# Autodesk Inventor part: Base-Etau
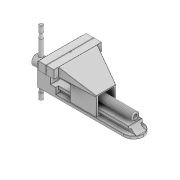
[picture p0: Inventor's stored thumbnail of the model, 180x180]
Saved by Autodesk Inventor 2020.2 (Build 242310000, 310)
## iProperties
Created: 2022-02
Part Number: Base-Etau
Material: Générique
Document SubType Name: Modeling
Designer: Philippe
Density: 1 g/cm^3
Appearance: Par défaut
Author: Philippe
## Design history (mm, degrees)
sketch "Esquisse1"
  geometry: L1 (0, 0)-(63.336, 0); L2 (0, 0)-(0, 50.188); L3 (-35.5, 12)-(-15, 12); L4 (-15, 12)-(-15, -22); L5 (-15, -22)-(-35.5, -22); L6 (-35.5, -22)-(-35.5, 12); L7 (-15, -22)-(113, -22); L8 (113, -22)-(113, -8); L9 (113, -8)-(-15, -8); L10 (-15, -8)-(-15, -22); L11 (0, 36)-(-12, 36); L12 (-12, 36)-(-12, 23); L13 (-12, 23)-(0, 23); L14 (0, 23)-(0, 36); L15 (0, 23)-(12, 23); L16 (12, 23)-(12, 36); L17 (12, 36)-(0, 36); L18 (0, 36)-(0, 23); L19 (15, 12)-(55.5, 12); L20 (55.5, 12)-(55.5, -17); L21 (55.5, -17)-(15, -17); L22 (15, -17)-(15, 12); L23 (55.5, 12)-(12, 36); L24 (55.5, 12)-(55.5, 36); L25 (55.5, 36)-(12, 36); L26 (12, 23)-(12, 10); L27 (12, 23)-(15, 10); L28 (15, 10)-(12, 10); 2 further points
  constraints: 56 end point, 10 parallel, 7 horizontal, 6 perpendicular, 4 collinear, 3 point on line, 2 vertical
  dimensions: "d0" = 22 distance between parallel lines of L7 L1; "d1" = 35.5 distance between parallel lines of L6 L2; "d2" = 20.5 distance between parallel lines of L4 L6; "d3" = 14 distance of L7.end L8.end; "d4" = 148.5 distance between parallel lines of L8 L6; "d5" = 34 distance of L5.end L3.start; "d8" = 12 distance of L11.start L11.end; "d9" = 13 distance of L11.end L12.end; "d10" = 44 distance between parallel lines of L9 L11; "d100" = 3 distance between parallel lines of L12 L4 (derived); "d101" = 3 distance between parallel lines of L22 L16 (derived); "d102" = 40.5 distance of L19.start L19.end; "d103" = 5 distance between parallel lines of L21 L7; "d123" = 2 distance from line of L27.end L19
extrude "Extrusion1" new body sketch "Esquisse1" stored distance "d6" = 30; taper "d7" = 0 deg
extrude "Extrusion2" join sketch "Esquisse1" stored distance "d11" = 74; taper "d12" = 0 deg
sketch "Esquisse8"
  geometry: L1 (0, 74)-(0, 0) reference; L2 (0, 7)-(-23.5, 7); L3 (-23.5, 7)-(-23.5, 67); L4 (-23.5, 67)-(0, 67); L5 (0, 67)-(0, 7); L6 (12, 74)-(12, 0) reference; L7 (-23.5, 52)-(-23.5, 22) reference; 4 further points
  constraints: 8 end point, 2 midpoint, 2 parallel, 1 collinear, 1 horizontal, 1 horizontal alignment, 1 perpendicular, 1 point on line
  dimensions: "d38" = 60 distance of L2.end L3.end
extrude "Extrusion3" join sketch "Esquisse8" distance "d39" = 26; taper "d40" = 0 deg
sketch "Esquisse9"
  geometry: L1 (-22, 45)-(-15, 45) reference; L2 (45, 45)-(52, 45) reference; L3 (0, 0)-(0, 32) reference; L4 (30, 32)-(30, 0) reference; L5 (-15, 45)-(0, 32); L6 (-22, 45)-(0, 0); L7 (52, 45)-(30, 0); L8 (45, 45)-(30, 32); 1 further point
  constraints: 8 end point
extrude "Extrusion4" cut sketch "Esquisse9" extent not by distance; stored distance "d41" = 0; taper "d42" = 0 deg
sketch "Esquisse10"
  geometry: L1 (0, 67)-(-23.5, 67) reference; L2 (-23.5, 7)-(0, 7) reference; L3 (0, 7)-(-23.5, 22); L4 (-23.5, 22)-(-23.5, 7); L5 (-23.5, 67)-(-23.5, 52); L6 (-23.5, 52)-(0, 67); 1 further point
  constraints: 8 end point, 2 vertical
extrude "Extrusion5" cut sketch "Esquisse10" extent not by distance; stored distance "d43" = 0; taper "d44" = 0 deg
sketch "Esquisse11"
  geometry: L1 (-35.5, 36)-(-12, 36) reference; L2 (-35.5, 36)-(-35.5, 12); L3 (-35.5, 12)-(-12, 36); L4 (-15, 10)-(-12, 10); L5 (-12, 10)-(-12, 23); L6 (-12.49, 22.598)-(-15, 10); A1 r 0.5 centre (-12, 22.5) between (-12, 23) and (-12.49, 22.598); 2 further points
  constraints: 10 end point, 2 point on circle, 1 centre point, 1 horizontal, 1 perpendicular, 1 point on line, 1 tangent, 1 vertical
  dimensions: "d47" = 0.5 radius of A1; "d48" = 2 distance of L2.end point (-35.5, 10)
extrude "Extrusion6" cut sketch "Esquisse11" extent not by distance; stored distance "d45" = 37; taper "d46" = 0 deg
sketch "Esquisse12"
  geometry: L1 (30, 14)-(0, 14) reference; L2 (0, 0)-(0, 14) reference; L3 (30, 0)-(0, 0) reference; L4 (30, 14)-(30, 0) reference; L5 (0, 14)-(4.35, 14); L6 (4.35, 14)-(4.35, 4.5); L7 (4.35, 4.5)-(0, 4.5); L8 (0, 4.5)-(0, 14); L9 (4.35, 4.5)-(7.5, 4.5); L10 (7.5, 4.5)-(7.5, 9.5); L11 (7.5, 9.5)-(4.35, 9.5); L12 (4.35, 9.5)-(4.35, 4.5); L13 (30, 14)-(25.65, 14); L14 (25.65, 14)-(25.65, 4.5); L15 (25.65, 4.5)-(30, 4.5); L16 (30, 4.5)-(30, 14); L17 (25.65, 4.5)-(22.5, 4.5); L18 (22.5, 4.5)-(22.5, 9.5); L19 (22.5, 9.5)-(25.65, 9.5); L20 (25.65, 9.5)-(25.65, 4.5); 3 further points
  constraints: 32 end point, 8 parallel, 4 horizontal, 4 perpendicular, 2 collinear, 2 point on line
  dimensions: "d49" = 9.5 distance of L5.end L6.end; "d50" = 5 distance of L9.end L10.end; "d51" = 15 distance between parallel lines of L18 L10; "d52" = 21.3 distance between parallel lines of L14 L6
extrude "Extrusion7" cut sketch "Esquisse12" distance "d53" = 120; taper "d54" = 0 deg
sketch "Esquisse13"
  geometry: L1 (148.5, -30)-(148.5, 0) reference; L2 (0, 0)-(148.5, 0) reference; L3 (148.5, -30)-(0, -30) reference; L4 (148.5, 0)-(132.531, 0); L5 (148.5, -30)-(132.531, -30); A1 r 16 centre (132.531, -16) between (148.5, -15) and (132.531, 0); A2 r 16 centre (132.531, -14) between (132.531, -30) and (148.5, -15); 1 further point
  constraints: 4 end point, 4 point on circle, 2 centre point, 2 point on line, 2 tangent, 1 equal radius, 1 midpoint
  dimensions: "d55" = 16 radius of A2
extrude "Extrusion8" cut sketch "Esquisse13" extent not by distance; stored distance "d56" = 10; taper "d57" = 0 deg
sketch "Esquisse14"
  geometry: L1 (110.587, -17.5)-(97.031, -17.5) reference; L2 (113, -8)-(113, -22) reference; L3 (113, -17.5)-(110.487, -17.5); L4 (107.998, -8)-(-7, -8) reference; L5 (113, -17.5)-(113, -8); L6 (113, -8)-(100.5, -8); A1 r 10 centre (110.487, -7.5) between (100.5, -8) and (110.487, -17.5); 1 further point
  constraints: 6 end point, 4 point on line, 2 point on circle, 1 centre point, 1 collinear, 1 perpendicular, 1 tangent
  dimensions: "d58" = 12.5 distance from line of L6.end L2; "d59" = 10 radius of A1
extrude "Extrusion9" cut sketch "Esquisse14" extent not by distance; stored distance "d60" = 37; taper "d61" = 0 deg
fillet "Congé1" dims "d62" = 0.5
fillet "Congé2" dims "d63" = 0.5
fillet "Congé3" dims "d64" = 0.5
fillet "Congé5" dims "d66" = 0.5
fillet "Congé6" dims "d67" = 0.5
fillet "Congé7" dims "d68" = 0.5
fillet "Congé8" dims "d69" = 0.5
sketch "Esquisse15"
  geometry: 1 further point
hole "Perçage1" sketch "Esquisse15" at (14.726, -11.796) diameter "d70" = 12.8; stored, may be unused: countersink angle "d74" = 90 deg, drill point angle "d76" = 118 deg; dims "d71" = 6, "d72" = 4, "d73" = 2, "d75" = 8
sketch "Esquisse16"
  geometry: L1 (-0.5, 29)-(-0.5, 0) reference; 2 further points
  constraints: 1 horizontal alignment
  dimensions: "d77" = 13 distance from line of L1 point (12.5, 14.5)
hole "Perçage2" sketch "Esquisse16" at (12.5, 14.5) diameter "d78" = 4.917; stored, may be unused: countersink angle "d82" = 90 deg, drill point angle "d84" = 118 deg; dims "d79" = 22, "d80" = 10.6, "d81" = 6.3, "d83" = 17.1
sketch "Esquisse17"
  geometry: L1 (45.5, 8.5)-(57.5, 8.5); L2 (57.5, 8.5)-(57.5, 20.5); L3 (57.5, 20.5)-(45.5, 20.5); L4 (45.5, 20.5)-(45.5, 8.5); L5 (45.5, 8.5)-(57.5, 20.5); L6 (57.5, 8.5)-(45.5, 20.5); C1 r 2.458 at (12.5, 14.5) reference; 3 further points
  constraints: 12 end point, 3 midpoint, 2 parallel, 1 horizontal, 1 horizontal alignment, 1 perpendicular
  dimensions: "d85" = 39 distance of C1.centre point (51.5, 14.5); "d86" = 12 distance of L1.end L2.end; "d87" = 12 distance of L2.end L3.end
extrude "Extrusion10" join sketch "Esquisse17" distance "d88" = 2; taper "d89" = 0 deg
sketch "Esquisse18"
  geometry: C1 r 5.3 at (-16, 10.15) reference; 2 further points
  constraints: 1 horizontal alignment
  dimensions: "d90" = 39 distance of C1.centre point (23, 10.15)
hole "Perçage3" sketch "Esquisse18" at (23, 10.15) diameter "d91" = 6.6; stored, may be unused: countersink angle "d95" = 90 deg, drill point angle "d97" = 118 deg; dims "d92" = 22, "d93" = 11, "d94" = 6.8, "d96" = 17.1
fillet "Congé9" dims "d98" = 0.5
fillet "Congé10" dims "d99" = 0.5
extrude "Extrusion11" new body sketch "Esquisse1" stored distance "d104" = 30; taper "d105" = 0 deg
extrude "Extrusion12" join sketch "Esquisse1" stored distance "d106" = 74; taper "d107" = 0 deg
sketch "Esquisse19"
  geometry: L1 (12, 67)-(55.5, 67); L2 (55.5, 67)-(55.5, 7); L3 (55.5, 7)-(12, 7); L4 (12, 7)-(12, 67); L5 (12, 74)-(12, 0) reference; L6 (55.5, 22)-(55.5, 52) reference; 2 further points
  constraints: 8 end point, 2 collinear, 2 midpoint, 2 parallel, 1 horizontal, 1 perpendicular
  dimensions: "d108" = 60 distance of L1.end L2.end
extrude "Extrusion13" join sketch "Esquisse19" distance "d109" = 26; taper "d110" = 0 deg
sketch "Esquisse20"
  geometry: L1 (0, 27)-(-15, 27) reference; L2 (45, 27)-(30, 27) reference; L3 (0, 27)-(-15, 40); L4 (-15, 40)-(-15, 27); L5 (30, 27)-(45, 40); L6 (45, 40)-(45, 27); 1 further point
  constraints: 8 end point, 1 parallel, 1 vertical
extrude "Extrusion14" cut sketch "Esquisse20" extent not by distance; stored distance "d111" = 57.5; taper "d112" = 0 deg
sketch "Esquisse21"
  geometry: L1 (55.5, 67)-(12, 67) reference; L2 (12, 7)-(55.5, 7) reference; L3 (12, 67)-(55.5, 52); L4 (55.5, 52)-(55.5, 67); L5 (12, 7)-(55.5, 22); L6 (55.5, 22)-(55.5, 7); 1 further point
  constraints: 8 end point, 1 collinear, 1 vertical
extrude "Extrusion15" cut sketch "Esquisse21" extent not by distance; stored distance "d113" = 0.182; taper "d114" = 0 deg
extrude "Extrusion16" cut sketch "Esquisse1" extent not by distance; stored distance "d115" = 37; taper "d116" = 0 deg
sketch "Esquisse22"
  geometry: L1 (3.25, 4)-(26.75, 4); L2 (26.75, 4)-(26.75, 27); L3 (26.75, 27)-(3.25, 27); L4 (3.25, 27)-(3.25, 4); L5 (3.25, 4)-(26.75, 27); L6 (26.75, 4)-(3.25, 27); L7 (6.75, 4)-(23.25, 4); L8 (23.25, 4)-(23.25, 0); L9 (23.25, 0)-(6.75, 0); L10 (6.75, 0)-(6.75, 4); L11 (6.75, 4)-(23.25, 0); L12 (23.25, 4)-(6.75, 0); L13 (30, 0)-(0, 0) reference; 8 further points
  constraints: 24 end point, 7 midpoint, 4 parallel, 2 collinear, 2 horizontal, 2 perpendicular, 2 vertical alignment
  dimensions: "d117" = 23.5 distance of L2.end L3.end; "d118" = 16.5 distance between parallel lines of L8 L10; "d119" = 4 distance of L7.end L8.end; "d120" = 23 distance of L1.end L2.end
extrude "Extrusion17" cut sketch "Esquisse22" extent not by distance; stored distance "d121" = 57.5; taper "d122" = 0 deg
fillet "Congé11" dims "d124" = 0.5, "d125" = 0.5
sketch "Esquisse23"
  geometry: L1 (18.5, 10)-(28.5, 10); L2 (28.5, 10)-(28.5, -7); L3 (28.5, -7)-(18.5, -7); L4 (18.5, -7)-(18.5, 10); L5 (15, 9.12)-(15, -12.5) reference; L6 (55, 10)-(15.88, 10) reference; 1 further point
  constraints: 8 end point, 2 parallel, 1 collinear, 1 horizontal, 1 perpendicular
  dimensions: "d126" = 10 distance of L1.start L1.end; "d127" = 3.5 distance between parallel lines of L5 L4; "d128" = 17 distance of L1.end L2.end
extrude "Extrusion18" join sketch "Esquisse23" stored distance "d129" = 28; taper "d130" = 0 deg
sketch "Esquisse24"
  geometry: L1 (11.5, 23)-(0.5, 23) reference; L2 (11.5, 23)-(32.5, 23); L3 (32.5, 23)-(32.5, 14.041); L4 (32.5, 14.041)-(25.5, 10); L5 (25.5, 10)-(11.5, 10); L6 (11.5, 10)-(11.5, 23); L7 (11.5, 10)-(18.5, 10); L8 (18.5, 10)-(18.5, -7); L9 (18.5, -7)-(11.5, -7); L10 (11.5, -7)-(11.5, 10); L11 (18.5, -7)-(18.5, 9.5) reference; L12 (18.5, 10)-(15.88, 10) reference; 2 further points
  constraints: 18 end point, 3 parallel, 3 perpendicular, 2 collinear, 2 horizontal
  dimensions: "d131" = 21 distance of L1.start L2.end; "d132" = 150 deg angle of L5 L4; "d133" = 7 distance from line of L4.end L8
extrude "Extrusion19" cut sketch "Esquisse24" stored distance "d134" = 24; taper "d135" = 0 deg
sketch "Esquisse25"
  geometry: 1 further point
hole "Perçage4" sketch "Esquisse25" at (12, 7) diameter "d136" = 10.106; stored, may be unused: countersink angle "d140" = 90 deg, drill point angle "d142" = 118 deg; dims "d137" = 24, "d138" = 10.6, "d139" = 6.3, "d141" = 32.3
sketch "Esquisse26"
  geometry: L1 (0, 30.5)-(0, 28.5); L2 (0, 28.5)-(1, 29.5); L3 (1, 29.5)-(0, 30.5); 1 further point
  constraints: 6 end point, 2 perpendicular, 1 point on line, 1 vertical
  dimensions: "d143" = 2 distance of L1.start L1.end; "d144" = 29.5 vertical distance of L2.end point (0, 0)
extrude "Extrusion20" cut sketch "Esquisse26" extent not by distance; stored distance "d145" = 37; taper "d146" = 0 deg
node "Plan de construction1"
fillet "Congé12" dims "d151" = 0.5
node "Axe de construction2"
pattern_circular "Réseau circulaire2" dims angle "d153" = 90 deg
sketch "Esquisse27"
  geometry: L1 (0, 0)-(-61.836, 0); L2 (-35.5, 0)-(-51.5, 0); L3 (-51.5, 0)-(-51.5, 8); L4 (-51.5, 8)-(-35.5, 8); L5 (-35.5, 8)-(-35.5, 0); L6 (-35.5, 0)-(101.5, 0); L7 (101.5, 0)-(101.5, 6); L8 (101.5, 6)-(-35.5, 6); L9 (-35.5, 6)-(-35.5, 0); L10 (-25.5, 6)-(-19.5, 6); L11 (-19.5, 6)-(-19.5, 3.5); L12 (-19.5, 3.5)-(-25.5, 3.5); L13 (-25.5, 3.5)-(-25.5, 6); L14 (-24.959, -15.7)-(-20.041, -15.7) reference; 6 further points
  constraints: 26 end point, 6 parallel, 4 horizontal, 3 perpendicular, 2 midpoint, 2 point on line, 1 vertical alignment
  dimensions: "d155" = 16 diameter of L4 L1; "d156" = 16 distance of L3.end L4.end; "d157" = 12 diameter of L8 L1; "d158" = 7 diameter of L12 L1; "d159" = 6 distance of L11.end L12.end; "d160" = 10 distance between parallel lines of L13 L5; "d161" = 153 distance between parallel lines of L7 L3
revolve "Révolution1" sketch "Esquisse27" stored, may be unused: angle "d162" = 90 deg
chamfer "Chanfrein1" distance "d163" = 1.5; stored, may be unused: second distance "d164" = 2, angle "d165" = 45 deg
feature "Filetage1" dims "d166" = 95, "d167" = 0
chamfer "Chanfrein2" distance "d168" = 0.5; stored, may be unused: second distance "d169" = 2, angle "d170" = 45 deg
sketch "Esquisse28"
  geometry: C1 r 4.5 at (0, 0) reference; 2 further points
  constraints: 1 coincident
hole "Perçage5" sketch "Esquisse28" at (0, 0) diameter "d171" = 4.917; stored, may be unused: countersink angle "d175" = 90 deg, drill point angle "d177" = 118 deg; dims "d172" = 12, "d173" = 4, "d174" = 2, "d176" = 16
chamfer "Chanfrein3" distance "d178" = 1; stored, may be unused: second distance "d179" = 2, angle "d180" = 45 deg
sketch "Esquisse29"
  geometry: L1 (-44.5, 8)-(-41.5, 8); L2 (-41.5, 8)-(-41.5, -8); L3 (-41.5, -8)-(-44.5, -8); L4 (-44.5, -8)-(-44.5, 8); L5 (-51.5, -7.5)-(-51.5, 7.5) reference; 2 further points
  constraints: 8 end point, 2 parallel, 1 horizontal, 1 horizontal alignment, 1 midpoint, 1 perpendicular
  dimensions: "d181" = 6 diameter of L2 L4; "d182" = 7 distance between parallel lines of L4 L5; "d183" = 16 distance of L3.end L1.start
revolve "Révolution2" sketch "Esquisse29" stored, may be unused: angle "d184" = 90 deg
chamfer "Chanfrein4" distance "d185" = 0.5; stored, may be unused: second distance "d186" = 2, angle "d187" = 45 deg
sketch "Esquisse30"
  geometry: C1 r 7.5 at (0, 0) reference; 2 further points
  constraints: 1 coincident
hole "Perçage6" sketch "Esquisse30" at (0, 0) diameter "d188" = 4.5; stored, may be unused: countersink angle "d192" = 90 deg, drill point angle "d194" = 118 deg; dims "d189" = 10, "d190" = 4, "d191" = 2, "d193" = 25
sketch "Esquisse31"
  geometry: L1 (-44.5, 0)-(-41.5, 0); L2 (-41.5, 0)-(-41.5, 50); L3 (-41.5, 50)-(-44.5, 50); L4 (-44.5, 50)-(-44.5, 0); L5 (-51.5, -7.5)-(-51.5, 7.5) reference; L6 (-41.5, 40)-(-42.5, 40); L7 (-42.5, 40)-(-41.5, 32); 1 further point
  constraints: 12 end point, 3 point on line, 2 horizontal, 2 parallel, 1 perpendicular
  dimensions: "d195" = 50 distance of L3.end L1.start; "d196" = 6 diameter of L2 L4; "d197" = 7 distance between parallel lines of L4 L5; "d198" = 10 distance between parallel lines of L3 L6; "d199" = 8 vertical distance of L6.end L7.end; "d200" = 4 diameter of L6.end L4
revolve "Révolution3" sketch "Esquisse31" stored, may be unused: angle "d201" = 90 deg
chamfer "Chanfrein5" distance "d202" = 1; stored, may be unused: second distance "d203" = 2, angle "d204" = 45 deg
mirror "Symétrie3"
sketch "Esquisse32"
  geometry: L1 (-41.5, 0)-(-38.1, 0); L2 (-38.1, 0)-(-38.1, 1.75); L3 (-38.1, 1.75)-(-41.5, 1.75); L4 (-41.5, 1.75)-(-41.5, 0); L5 (-38.1, 0)-(-35.1, 0); L6 (-35.1, 0)-(-35.1, 1); L7 (-35.1, 1)-(-38.1, 1); L8 (-38.1, 1)-(-38.1, 0); 2 further points
  constraints: 17 end point, 4 parallel, 2 horizontal, 2 perpendicular, 1 point on line
  dimensions: "d205" = 3.5 diameter of L3 L1; "d206" = 3.4 distance of L2.end L3.end; "d207" = 3 distance of L6.end L7.end; "d208" = 2 diameter of L7 L5; "d209" = 41.5 distance from line of L4 point (0, 0)
revolve "Révolution4" sketch "Esquisse32" stored, may be unused: angle "d210" = 90 deg
node "01-Mors fixe"
node "Boucle projetée4"
node "02-Mors mobile"
node "03-Vis de blocage Mors"
node "05-Levier de blocage Mors"
node "06-Verrou de blocage Levier"
other parameters: "d147" = 29.5
